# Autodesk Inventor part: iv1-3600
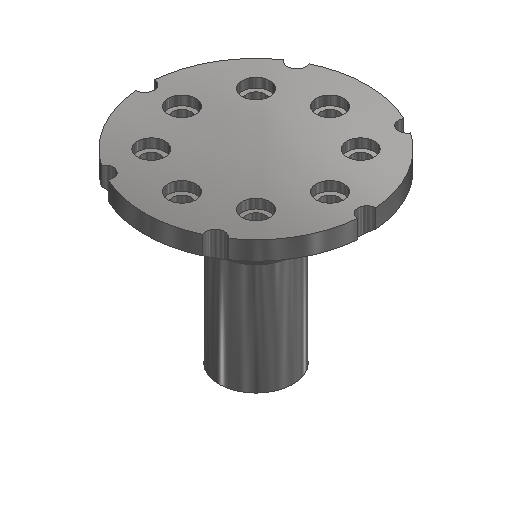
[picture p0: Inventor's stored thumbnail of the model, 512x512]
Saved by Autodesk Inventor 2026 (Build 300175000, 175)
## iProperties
Created: 2004-09
Part Number: iv1-3600
Document SubType Name: Modeling
Designer: Lars Bertram Pedersen
Manufacturer: Standard
Standards Organization: Custom
Material: Steel, Mild
Density: 7.85 g/cm^3
Appearance: Semi-Polished
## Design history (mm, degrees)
revolve "Revolution1" stored, may be unused: angle "d5" = 90 deg
sketch "Sketch2"
  geometry: C1 r 5 at (0, 60); 1 further point
  constraints: 2 vertical alignment, 1 centre point, 1 other
  dimensions: "d7" = 10 diameter of C1
extrude "Extrusion1" cut sketch "Sketch2" extent not by distance; stored distance "d8" = 10; taper "d9" = 0 deg
pattern_circular "Circular Pattern1" dims angle "d12" = 360 deg
sketch "Sketch3"
  geometry: 2 further points
  constraints: 1 vertical alignment
  dimensions: "d21" = 40 distance of point (0, -20) point (0, -60)
hole "Hole2" sketch "Sketch3" diameter "d22" = 10; stored, may be unused: countersink angle "d26" = 90 deg, drill point angle "d28" = 118 deg; dims "d23" = 6, "d24" = 15, "d25" = 5, "d27" = 20
pattern_circular "Circular Pattern2" dims angle "d31" = 360 deg
body "Solid1"
sketch "Sketch1"
  geometry: L1 (0, 100)-(60, 100); L2 (60, 100)-(60, 90); L3 (60, 90)-(20, 60); L4 (20, 60)-(20, 0); L5 (20, 0)-(0, 0); L6 (0, 0)-(0, 100); 1 further point
  constraints: 12 end point, 3 parallel, 1 coincident, 1 horizontal, 1 perpendicular
  dimensions: "d0" = 10 distance of L1.end L2.end; "d1" = 60 distance of L1.start L1.end; "d2" = 20 distance of L4.end L5.end; "d3" = 60 distance of L3.end L4.end; "d4" = 100 distance of L5.end L1.start
